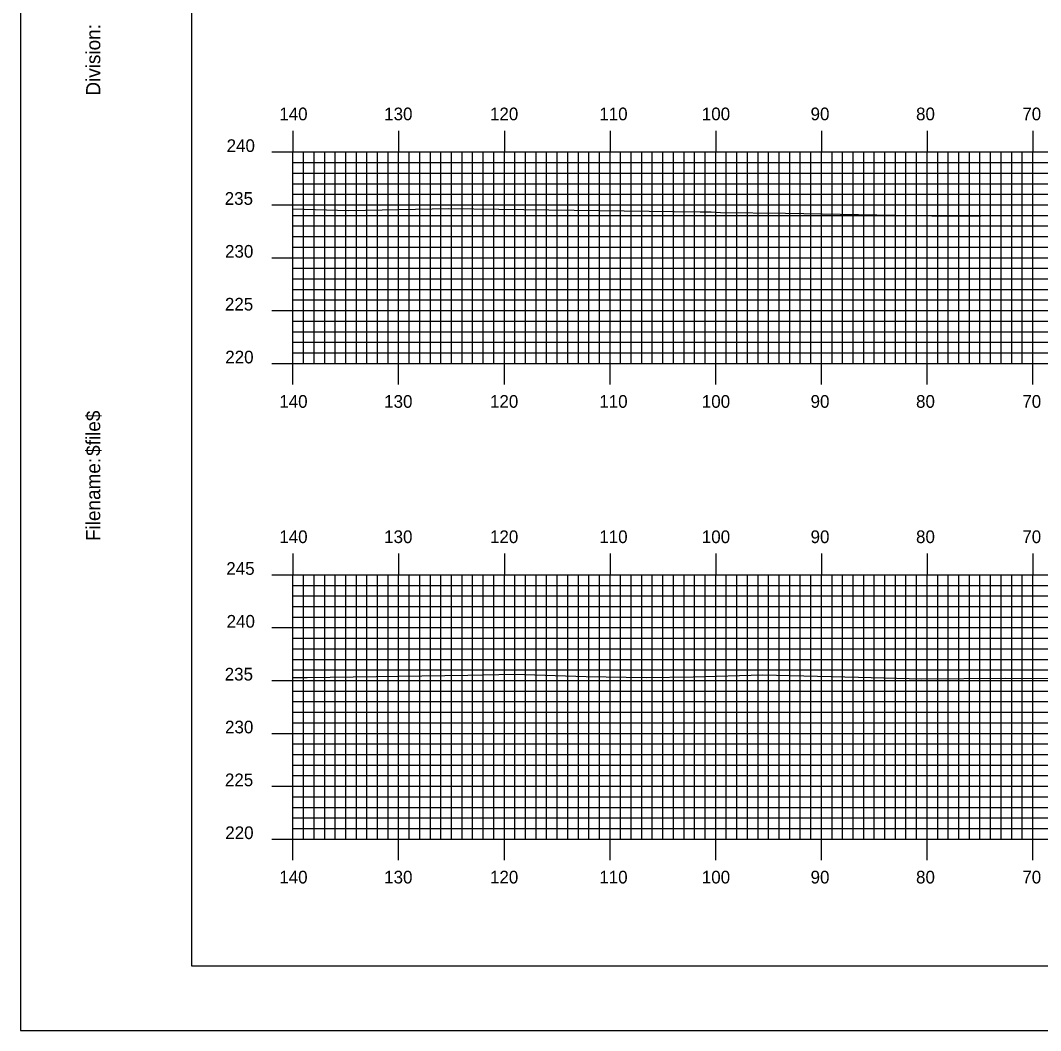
# Model space of a CAD drawing. Extents: x 1803110 to 1803453, y 442591 to 442811.
# Drawn here: x 1803109.8 to 1803206.4, y 442590.5 to 442686.1 of the extents above; entities that cross this region are included whole.
import ezdxf

# ---------------------------------------------------------------- set-up
doc = ezdxf.new("R2010")
doc.units = 0
for name, color, linetype in [('BORDER', 7, 'Continuous'), ('H_V ANNOTATION', 7, 'Continuous'), ('MAJOR', 7, 'Continuous'), ('MINOR', 7, 'Continuous'), ('PLOT BOUNDARY', 7, 'Continuous'), ('S_Roadway_Centerline', 7, 'Continuous')]:
    doc.layers.add(name, color=color, linetype=linetype)

msp = doc.modelspace()

# ---------------------------------------------------------------- linework, layer by layer
at = {"layer": 'BORDER'}
msp.add_lwpolyline([(1803126.028, 442596.665), (1803446.028, 442596.665), (1803446.028, 442806.665), (1803126.028, 442806.665)], close=True, dxfattribs=at)
at = {"layer": 'MAJOR'}
for p, q in [((1803135.628, 442675.669), (1803135.628, 442673.665)), ((1803145.628, 442675.669), (1803145.628, 442673.665)), ((1803155.628, 442675.669), (1803155.628, 442673.665)), ((1803165.628, 442675.669), (1803165.628, 442673.665)), ((1803175.628, 442675.669), (1803175.628, 442673.665)), ((1803185.628, 442675.669), (1803185.628, 442673.665)), ((1803195.628, 442675.669), (1803195.628, 442673.665)), ((1803205.628, 442675.669), (1803205.628, 442673.665)), ((1803133.624, 442673.665), (1803135.628, 442673.665)), ((1803135.628, 442673.665), (1803415.628, 442673.665)), ((1803135.628, 442653.665), (1803135.628, 442673.665)), ((1803135.628, 442653.665), (1803135.628, 442673.665)), ((1803135.628, 442673.665), (1803415.628, 442673.665)), ((1803145.628, 442653.665), (1803145.628, 442673.665)), ((1803155.628, 442653.665), (1803155.628, 442673.665)), ((1803165.628, 442653.665), (1803165.628, 442673.665)), ((1803175.628, 442653.665), (1803175.628, 442673.665)), ((1803185.628, 442653.665), (1803185.628, 442673.665)), ((1803195.628, 442653.665), (1803195.628, 442673.665)), ((1803205.628, 442653.665), (1803205.628, 442673.665)), ((1803133.624, 442668.665), (1803135.628, 442668.665)), ((1803135.628, 442668.665), (1803415.628, 442668.665)), ((1803133.624, 442663.665), (1803135.628, 442663.665)), ((1803135.628, 442663.665), (1803415.628, 442663.665)), ((1803133.624, 442658.665), (1803135.628, 442658.665)), ((1803135.628, 442658.665), (1803415.628, 442658.665)), ((1803133.624, 442653.665), (1803135.628, 442653.665)), ((1803135.628, 442653.665), (1803415.628, 442653.665)), ((1803135.628, 442653.665), (1803415.628, 442653.665)), ((1803135.628, 442651.661), (1803135.628, 442653.665)), ((1803145.628, 442651.661), (1803145.628, 442653.665)), ((1803155.628, 442651.661), (1803155.628, 442653.665)), ((1803165.628, 442651.661), (1803165.628, 442653.665)), ((1803175.628, 442651.661), (1803175.628, 442653.665)), ((1803185.628, 442651.661), (1803185.628, 442653.665)), ((1803195.628, 442651.661), (1803195.628, 442653.665)), ((1803205.628, 442651.661), (1803205.628, 442653.665)), ((1803135.628, 442635.669), (1803135.628, 442633.665)), ((1803145.628, 442635.669), (1803145.628, 442633.665)), ((1803155.628, 442635.669), (1803155.628, 442633.665)), ((1803165.628, 442635.669), (1803165.628, 442633.665)), ((1803175.628, 442635.669), (1803175.628, 442633.665)), ((1803185.628, 442635.669), (1803185.628, 442633.665)), ((1803195.628, 442635.669), (1803195.628, 442633.665)), ((1803205.628, 442635.669), (1803205.628, 442633.665)), ((1803133.624, 442633.665), (1803135.628, 442633.665)), ((1803135.628, 442633.665), (1803415.628, 442633.665)), ((1803135.628, 442608.665), (1803135.628, 442633.665)), ((1803135.628, 442608.665), (1803135.628, 442633.665)), ((1803135.628, 442633.665), (1803415.628, 442633.665)), ((1803145.628, 442608.665), (1803145.628, 442633.665)), ((1803155.628, 442608.665), (1803155.628, 442633.665)), ((1803165.628, 442608.665), (1803165.628, 442633.665)), ((1803175.628, 442608.665), (1803175.628, 442633.665)), ((1803185.628, 442608.665), (1803185.628, 442633.665)), ((1803195.628, 442608.665), (1803195.628, 442633.665)), ((1803205.628, 442608.665), (1803205.628, 442633.665)), ((1803133.624, 442628.665), (1803135.628, 442628.665)), ((1803135.628, 442628.665), (1803415.628, 442628.665)), ((1803133.624, 442623.665), (1803135.628, 442623.665)), ((1803135.628, 442623.665), (1803415.628, 442623.665)), ((1803133.624, 442618.665), (1803135.628, 442618.665)), ((1803135.628, 442618.665), (1803415.628, 442618.665)), ((1803133.624, 442613.665), (1803135.628, 442613.665)), ((1803135.628, 442613.665), (1803415.628, 442613.665)), ((1803133.624, 442608.665), (1803135.628, 442608.665)), ((1803135.628, 442608.665), (1803415.628, 442608.665)), ((1803135.628, 442608.665), (1803415.628, 442608.665)), ((1803135.628, 442606.661), (1803135.628, 442608.665)), ((1803145.628, 442606.661), (1803145.628, 442608.665)), ((1803155.628, 442606.661), (1803155.628, 442608.665)), ((1803165.628, 442606.661), (1803165.628, 442608.665)), ((1803175.628, 442606.661), (1803175.628, 442608.665)), ((1803185.628, 442606.661), (1803185.628, 442608.665)), ((1803195.628, 442606.661), (1803195.628, 442608.665)), ((1803205.628, 442606.661), (1803205.628, 442608.665))]:
    msp.add_line(p, q, dxfattribs=at)
at = {"layer": 'MINOR'}
for p, q in [((1803136.628, 442653.665), (1803136.628, 442673.665)), ((1803137.628, 442653.665), (1803137.628, 442673.665)), ((1803138.628, 442653.665), (1803138.628, 442673.665)), ((1803139.628, 442653.665), (1803139.628, 442673.665)), ((1803140.628, 442653.665), (1803140.628, 442673.665)), ((1803141.628, 442653.665), (1803141.628, 442673.665)), ((1803142.628, 442653.665), (1803142.628, 442673.665)), ((1803143.628, 442653.665), (1803143.628, 442673.665)), ((1803144.628, 442653.665), (1803144.628, 442673.665)), ((1803146.628, 442653.665), (1803146.628, 442673.665)), ((1803147.628, 442653.665), (1803147.628, 442673.665)), ((1803148.628, 442653.665), (1803148.628, 442673.665)), ((1803149.628, 442653.665), (1803149.628, 442673.665)), ((1803150.628, 442653.665), (1803150.628, 442673.665)), ((1803151.628, 442653.665), (1803151.628, 442673.665)), ((1803152.628, 442653.665), (1803152.628, 442673.665)), ((1803153.628, 442653.665), (1803153.628, 442673.665)), ((1803154.628, 442653.665), (1803154.628, 442673.665)), ((1803156.628, 442653.665), (1803156.628, 442673.665)), ((1803157.628, 442653.665), (1803157.628, 442673.665)), ((1803158.628, 442653.665), (1803158.628, 442673.665)), ((1803159.628, 442653.665), (1803159.628, 442673.665)), ((1803160.628, 442653.665), (1803160.628, 442673.665)), ((1803161.628, 442653.665), (1803161.628, 442673.665)), ((1803162.628, 442653.665), (1803162.628, 442673.665)), ((1803163.628, 442653.665), (1803163.628, 442673.665)), ((1803164.628, 442653.665), (1803164.628, 442673.665)), ((1803166.628, 442653.665), (1803166.628, 442673.665)), ((1803167.628, 442653.665), (1803167.628, 442673.665)), ((1803168.628, 442653.665), (1803168.628, 442673.665)), ((1803169.628, 442653.665), (1803169.628, 442673.665)), ((1803170.628, 442653.665), (1803170.628, 442673.665)), ((1803171.628, 442653.665), (1803171.628, 442673.665)), ((1803172.628, 442653.665), (1803172.628, 442673.665)), ((1803173.628, 442653.665), (1803173.628, 442673.665)), ((1803174.628, 442653.665), (1803174.628, 442673.665)), ((1803176.628, 442653.665), (1803176.628, 442673.665)), ((1803177.628, 442653.665), (1803177.628, 442673.665)), ((1803178.628, 442653.665), (1803178.628, 442673.665)), ((1803179.628, 442653.665), (1803179.628, 442673.665)), ((1803180.628, 442653.665), (1803180.628, 442673.665)), ((1803181.628, 442653.665), (1803181.628, 442673.665)), ((1803182.628, 442653.665), (1803182.628, 442673.665)), ((1803183.628, 442653.665), (1803183.628, 442673.665)), ((1803184.628, 442653.665), (1803184.628, 442673.665)), ((1803186.628, 442653.665), (1803186.628, 442673.665)), ((1803187.628, 442653.665), (1803187.628, 442673.665)), ((1803188.628, 442653.665), (1803188.628, 442673.665)), ((1803189.628, 442653.665), (1803189.628, 442673.665)), ((1803190.628, 442653.665), (1803190.628, 442673.665)), ((1803191.628, 442653.665), (1803191.628, 442673.665)), ((1803192.628, 442653.665), (1803192.628, 442673.665)), ((1803193.628, 442653.665), (1803193.628, 442673.665)), ((1803194.628, 442653.665), (1803194.628, 442673.665)), ((1803196.628, 442653.665), (1803196.628, 442673.665)), ((1803197.628, 442653.665), (1803197.628, 442673.665)), ((1803198.628, 442653.665), (1803198.628, 442673.665)), ((1803199.628, 442653.665), (1803199.628, 442673.665)), ((1803200.628, 442653.665), (1803200.628, 442673.665)), ((1803201.628, 442653.665), (1803201.628, 442673.665)), ((1803202.628, 442653.665), (1803202.628, 442673.665)), ((1803203.628, 442653.665), (1803203.628, 442673.665)), ((1803204.628, 442653.665), (1803204.628, 442673.665)), ((1803135.628, 442672.665), (1803415.628, 442672.665)), ((1803135.628, 442672.665), (1803137.632, 442672.665)), ((1803135.628, 442671.665), (1803415.628, 442671.665)), ((1803135.628, 442671.665), (1803137.632, 442671.665)), ((1803135.628, 442670.665), (1803415.628, 442670.665)), ((1803135.628, 442670.665), (1803137.632, 442670.665)), ((1803135.628, 442669.665), (1803415.628, 442669.665)), ((1803135.628, 442669.665), (1803137.632, 442669.665)), ((1803135.628, 442667.665), (1803415.628, 442667.665)), ((1803135.628, 442667.665), (1803137.632, 442667.665)), ((1803135.628, 442666.665), (1803415.628, 442666.665)), ((1803135.628, 442666.665), (1803137.632, 442666.665)), ((1803135.628, 442665.665), (1803415.628, 442665.665)), ((1803135.628, 442665.665), (1803137.632, 442665.665)), ((1803135.628, 442664.665), (1803415.628, 442664.665)), ((1803135.628, 442664.665), (1803137.632, 442664.665)), ((1803135.628, 442662.665), (1803415.628, 442662.665)), ((1803135.628, 442662.665), (1803137.632, 442662.665)), ((1803135.628, 442661.665), (1803415.628, 442661.665)), ((1803135.628, 442661.665), (1803137.632, 442661.665)), ((1803135.628, 442660.665), (1803415.628, 442660.665)), ((1803135.628, 442660.665), (1803137.632, 442660.665)), ((1803135.628, 442659.665), (1803415.628, 442659.665)), ((1803135.628, 442659.665), (1803137.632, 442659.665)), ((1803135.628, 442657.665), (1803415.628, 442657.665)), ((1803135.628, 442657.665), (1803137.632, 442657.665)), ((1803135.628, 442656.665), (1803415.628, 442656.665)), ((1803135.628, 442656.665), (1803137.632, 442656.665)), ((1803135.628, 442655.665), (1803415.628, 442655.665)), ((1803135.628, 442655.665), (1803137.632, 442655.665)), ((1803135.628, 442654.665), (1803415.628, 442654.665)), ((1803135.628, 442654.665), (1803137.632, 442654.665)), ((1803136.628, 442608.665), (1803136.628, 442633.665)), ((1803137.628, 442608.665), (1803137.628, 442633.665)), ((1803138.628, 442608.665), (1803138.628, 442633.665)), ((1803139.628, 442608.665), (1803139.628, 442633.665)), ((1803140.628, 442608.665), (1803140.628, 442633.665)), ((1803141.628, 442608.665), (1803141.628, 442633.665)), ((1803142.628, 442608.665), (1803142.628, 442633.665)), ((1803143.628, 442608.665), (1803143.628, 442633.665)), ((1803144.628, 442608.665), (1803144.628, 442633.665)), ((1803146.628, 442608.665), (1803146.628, 442633.665)), ((1803147.628, 442608.665), (1803147.628, 442633.665)), ((1803148.628, 442608.665), (1803148.628, 442633.665)), ((1803149.628, 442608.665), (1803149.628, 442633.665)), ((1803150.628, 442608.665), (1803150.628, 442633.665)), ((1803151.628, 442608.665), (1803151.628, 442633.665)), ((1803152.628, 442608.665), (1803152.628, 442633.665)), ((1803153.628, 442608.665), (1803153.628, 442633.665)), ((1803154.628, 442608.665), (1803154.628, 442633.665)), ((1803156.628, 442608.665), (1803156.628, 442633.665)), ((1803157.628, 442608.665), (1803157.628, 442633.665)), ((1803158.628, 442608.665), (1803158.628, 442633.665)), ((1803159.628, 442608.665), (1803159.628, 442633.665)), ((1803160.628, 442608.665), (1803160.628, 442633.665)), ((1803161.628, 442608.665), (1803161.628, 442633.665)), ((1803162.628, 442608.665), (1803162.628, 442633.665)), ((1803163.628, 442608.665), (1803163.628, 442633.665)), ((1803164.628, 442608.665), (1803164.628, 442633.665)), ((1803166.628, 442608.665), (1803166.628, 442633.665)), ((1803167.628, 442608.665), (1803167.628, 442633.665)), ((1803168.628, 442608.665), (1803168.628, 442633.665)), ((1803169.628, 442608.665), (1803169.628, 442633.665)), ((1803170.628, 442608.665), (1803170.628, 442633.665)), ((1803171.628, 442608.665), (1803171.628, 442633.665)), ((1803172.628, 442608.665), (1803172.628, 442633.665)), ((1803173.628, 442608.665), (1803173.628, 442633.665)), ((1803174.628, 442608.665), (1803174.628, 442633.665)), ((1803176.628, 442608.665), (1803176.628, 442633.665)), ((1803177.628, 442608.665), (1803177.628, 442633.665)), ((1803178.628, 442608.665), (1803178.628, 442633.665)), ((1803179.628, 442608.665), (1803179.628, 442633.665)), ((1803180.628, 442608.665), (1803180.628, 442633.665)), ((1803181.628, 442608.665), (1803181.628, 442633.665)), ((1803182.628, 442608.665), (1803182.628, 442633.665)), ((1803183.628, 442608.665), (1803183.628, 442633.665)), ((1803184.628, 442608.665), (1803184.628, 442633.665)), ((1803186.628, 442608.665), (1803186.628, 442633.665)), ((1803187.628, 442608.665), (1803187.628, 442633.665)), ((1803188.628, 442608.665), (1803188.628, 442633.665)), ((1803189.628, 442608.665), (1803189.628, 442633.665)), ((1803190.628, 442608.665), (1803190.628, 442633.665)), ((1803191.628, 442608.665), (1803191.628, 442633.665)), ((1803192.628, 442608.665), (1803192.628, 442633.665)), ((1803193.628, 442608.665), (1803193.628, 442633.665)), ((1803194.628, 442608.665), (1803194.628, 442633.665)), ((1803196.628, 442608.665), (1803196.628, 442633.665)), ((1803197.628, 442608.665), (1803197.628, 442633.665)), ((1803198.628, 442608.665), (1803198.628, 442633.665)), ((1803199.628, 442608.665), (1803199.628, 442633.665)), ((1803200.628, 442608.665), (1803200.628, 442633.665)), ((1803201.628, 442608.665), (1803201.628, 442633.665)), ((1803202.628, 442608.665), (1803202.628, 442633.665)), ((1803203.628, 442608.665), (1803203.628, 442633.665)), ((1803204.628, 442608.665), (1803204.628, 442633.665)), ((1803135.628, 442632.665), (1803415.628, 442632.665)), ((1803135.628, 442632.665), (1803137.632, 442632.665)), ((1803135.628, 442631.665), (1803415.628, 442631.665)), ((1803135.628, 442631.665), (1803137.632, 442631.665)), ((1803135.628, 442630.665), (1803415.628, 442630.665)), ((1803135.628, 442630.665), (1803137.632, 442630.665)), ((1803135.628, 442629.665), (1803415.628, 442629.665)), ((1803135.628, 442629.665), (1803137.632, 442629.665)), ((1803135.628, 442627.665), (1803415.628, 442627.665)), ((1803135.628, 442627.665), (1803137.632, 442627.665)), ((1803135.628, 442626.665), (1803415.628, 442626.665)), ((1803135.628, 442626.665), (1803137.632, 442626.665)), ((1803135.628, 442625.665), (1803415.628, 442625.665)), ((1803135.628, 442625.665), (1803137.632, 442625.665)), ((1803135.628, 442624.665), (1803415.628, 442624.665)), ((1803135.628, 442624.665), (1803137.632, 442624.665)), ((1803135.628, 442622.665), (1803415.628, 442622.665)), ((1803135.628, 442622.665), (1803137.632, 442622.665)), ((1803135.628, 442621.665), (1803415.628, 442621.665)), ((1803135.628, 442621.665), (1803137.632, 442621.665)), ((1803135.628, 442620.665), (1803415.628, 442620.665)), ((1803135.628, 442620.665), (1803137.632, 442620.665)), ((1803135.628, 442619.665), (1803415.628, 442619.665)), ((1803135.628, 442619.665), (1803137.632, 442619.665)), ((1803135.628, 442617.665), (1803415.628, 442617.665)), ((1803135.628, 442617.665), (1803137.632, 442617.665)), ((1803135.628, 442616.665), (1803415.628, 442616.665)), ((1803135.628, 442616.665), (1803137.632, 442616.665)), ((1803135.628, 442615.665), (1803415.628, 442615.665)), ((1803135.628, 442615.665), (1803137.632, 442615.665)), ((1803135.628, 442614.665), (1803415.628, 442614.665)), ((1803135.628, 442614.665), (1803137.632, 442614.665)), ((1803135.628, 442612.665), (1803415.628, 442612.665)), ((1803135.628, 442612.665), (1803137.632, 442612.665)), ((1803135.628, 442611.665), (1803415.628, 442611.665)), ((1803135.628, 442611.665), (1803137.632, 442611.665)), ((1803135.628, 442610.665), (1803415.628, 442610.665)), ((1803135.628, 442610.665), (1803137.632, 442610.665)), ((1803135.628, 442609.665), (1803415.628, 442609.665)), ((1803135.628, 442609.665), (1803137.632, 442609.665))]:
    msp.add_line(p, q, dxfattribs=at)
at = {"layer": 'PLOT BOUNDARY'}
msp.add_lwpolyline([(1803109.841, 442590.547), (1803449.841, 442590.547), (1803449.841, 442810.547), (1803109.841, 442810.547)], close=True, dxfattribs=at)
at = {"layer": 'S_Roadway_Centerline'}
for points in [[(1803135.628, 442668.273), (1803140.928, 442668.139), (1803150.386, 442668.318), (1803171.682, 442668.023), (1803174.164, 442667.992), (1803175.204, 442667.99), (1803176.089, 442667.953), (1803182.222, 442667.874), (1803196.073, 442667.613), (1803200.699, 442667.635), (1803217.193, 442667.669)], [(1803135.628, 442623.94), (1803136.961, 442623.937), (1803152.158, 442624.164), (1803156.548, 442624.26), (1803163.36, 442624.059), (1803169.042, 442623.961), (1803173.477, 442624.01), (1803180.085, 442624.21), (1803189.125, 442623.995), (1803195.139, 442623.839), (1803203.03, 442623.873), (1803209.311, 442623.844)]]:
    msp.add_lwpolyline(points, dxfattribs=at)

# ---------------------------------------------------------------- texts
at = {"layer": 'BORDER'}
for s, p in [('Division:', (1803117.398, 442678.997)), ('$file$', (1803117.398, 442644.916)), ('Filename:', (1803117.398, 442636.862))]:
    msp.add_text(s, height=1.3392, rotation=90, dxfattribs=at).set_placement(p)
at = {"layer": 'H_V ANNOTATION'}
for s, p in [('140', (1803134.333, 442676.665)), ('130', (1803144.258, 442676.665)), ('120', (1803154.268, 442676.665)), ('110', (1803164.611, 442676.665)), ('100', (1803174.311, 442676.665)), ('90', (1803184.6, 442676.665)), ('80', (1803194.579, 442676.665)), ('70', (1803204.632, 442676.665)), ('240', (1803129.352, 442673.665)), ('235', (1803129.17, 442668.665)), ('230', (1803129.202, 442663.665)), ('225', (1803129.191, 442658.665)), ('220', (1803129.223, 442653.665)), ('140', (1803134.333, 442649.465)), ('130', (1803144.258, 442649.465)), ('120', (1803154.268, 442649.465)), ('110', (1803164.611, 442649.465)), ('100', (1803174.311, 442649.465)), ('90', (1803184.6, 442649.465)), ('80', (1803194.579, 442649.465)), ('70', (1803204.632, 442649.465)), ('140', (1803134.333, 442636.665)), ('130', (1803144.258, 442636.665)), ('120', (1803154.268, 442636.665)), ('110', (1803164.611, 442636.665)), ('100', (1803174.311, 442636.665)), ('90', (1803184.6, 442636.665)), ('80', (1803194.579, 442636.665)), ('70', (1803204.632, 442636.665)), ('245', (1803129.32, 442633.665)), ('240', (1803129.352, 442628.665)), ('235', (1803129.17, 442623.665)), ('230', (1803129.202, 442618.665)), ('225', (1803129.191, 442613.665)), ('220', (1803129.223, 442608.665)), ('140', (1803134.333, 442604.465)), ('130', (1803144.258, 442604.465)), ('120', (1803154.268, 442604.465)), ('110', (1803164.611, 442604.465)), ('100', (1803174.311, 442604.465)), ('90', (1803184.6, 442604.465)), ('80', (1803194.579, 442604.465)), ('70', (1803204.632, 442604.465))]:
    msp.add_text(s, height=1.2, dxfattribs=at).set_placement(p)
at = {"layer": 'MAJOR'}
for p in [(1803135.619, 442653.665), (1803135.619, 442608.665)]:
    msp.add_text('-', height=0.012, dxfattribs=at).set_placement(p)

doc.saveas('drawing.dxf')
